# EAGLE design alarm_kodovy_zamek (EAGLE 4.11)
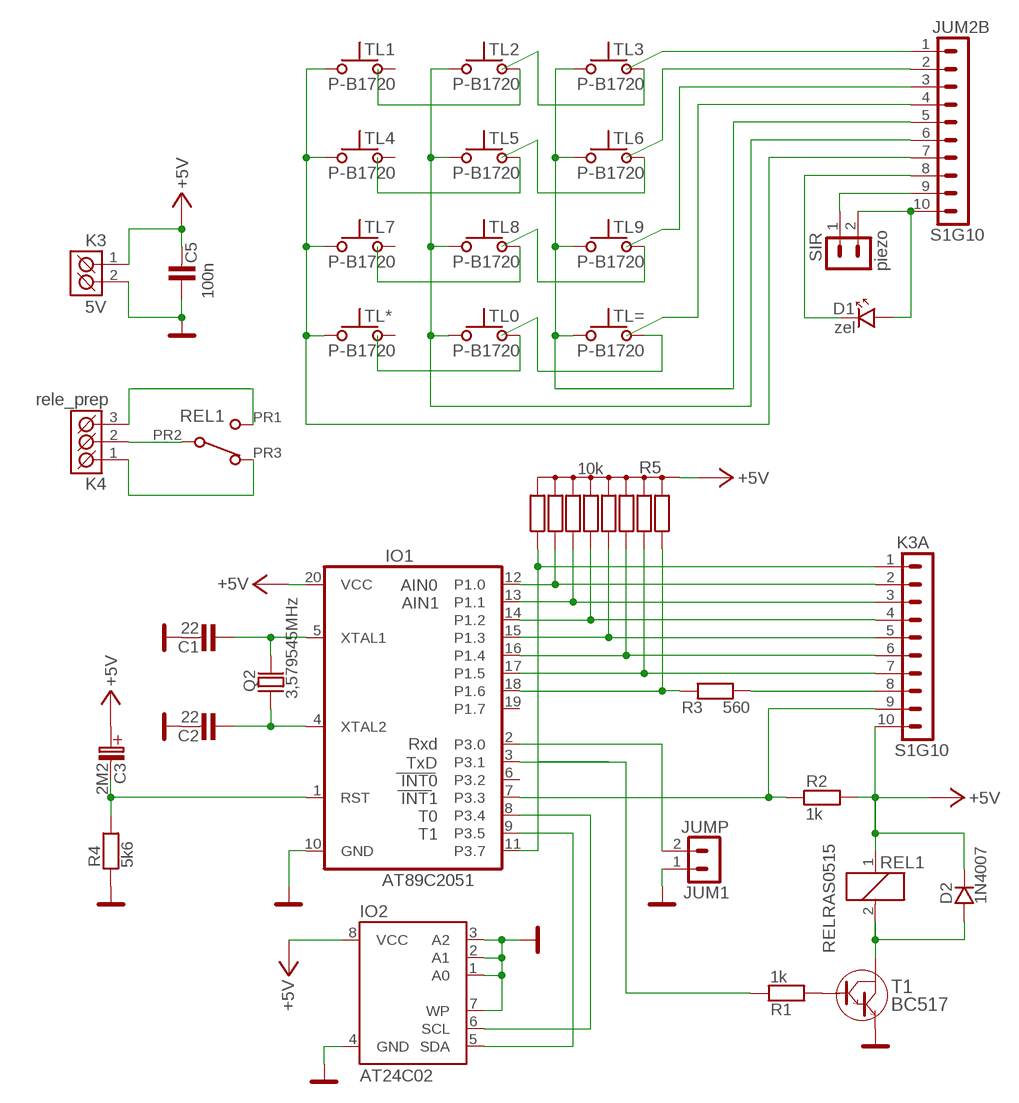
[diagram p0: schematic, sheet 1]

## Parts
C1  22  C-KERAMIK_5  [C-5]
C2  22  C-KERAMIK_5  [C-5]
C3  2M2  C-ELEKTROLYT_2  [C-EL_2]
C5  100n  C-KERAMIK_SMD_1206  [1206]
D1  zel  LED_3  [LED_3]
D2  1N4007  1N4007_SMD_SM-1  [SM-1]
IO1  AT89C2051  [DIL20]
IO2  AT24C02  AT24CP  [DIL08]
JUM1  JUMP  S1G2_JUMP  [S1G2_JUM]
JUM2B  S1G10  S1G10_JUMP  [S1G10_JU]
K3  5V  ARK500/2  [ARK500/2]
K3A  S1G10  S1G10_JUMP  [S1G10_JU]
K4  rele_prep  ARK500/3  [ARK500/3]
Q2  3,579545MHz  Q_HC-49U  [HC-49U]
R1  1k  R_SMD_1206  [1206]
R2  1k  R_SMD_1206  [1206]
R3  560  R_SMD_1206  [1206]
R4  5k6  R_7,5  [R-7,5]
R5  10k  RR_8X_A  [RR_8X_A]
REL1  RELRAS0515  RELRAS15  [RELE_RAS]
SIR  piezo  S1G2_JUMP  [S1G2_JUM]
T1  BC517  [TO-92]
TL0  P-B1720  [P-B1720]
TL1  P-B1720  [P-B1720]
TL2  P-B1720  [P-B1720]
TL3  P-B1720  [P-B1720]
TL4  P-B1720  [P-B1720]
TL5  P-B1720  [P-B1720]
TL6  P-B1720  [P-B1720]
TL7  P-B1720  [P-B1720]
TL8  P-B1720  [P-B1720]
TL9  P-B1720  [P-B1720]
TL*  P-B1720  [P-B1720]
TL=  P-B1720  [P-B1720]

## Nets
+5V: C3.C+(C_EL+) C5.2 D2.K IO1.20(VCC) IO2.8(VCC) K3.1(K1) K3A.10 R2.2 R5.1(R) REL1.1(RE:C1)
GND: C1.2 C2.2 C5.1 IO1.10(GND) IO2.1(A0) IO2.2(A1) IO2.3(A2) IO2.4(GND) IO2.7(WP) JUM1.1 K3.2(K2) R4.1 T1.3(E)
K3B: D1.A JUM2B.10 SIR.2
N$1: IO1.11(P3.7) K3A.1 R5.9(R8)
N$2: IO1.18(P1.6) R3.1 R5.2(R1)
N$3: C1.1 IO1.5(XTAL1) Q2.2
N$4: C2.1 IO1.4(XTAL2) Q2.1
N$5: IO1.12(P1.0) K3A.2 R5.8(R7)
N$6: IO1.13(P1.1) K3A.3 R5.7(R6)
N$7: IO1.14(P1.2) K3A.4 R5.6(R5)
N$8: IO1.15(P1.3) K3A.5 R5.5(R4)
N$9: IO1.16(P1.4) K3A.6 R5.4(R3)
N$10: IO1.17(P1.5) K3A.7 R5.3(R2)
N$11: C3.C-(C_EL-) IO1.1(RST) R4.2
N$12: K4.3(K3) REL1.PR1
N$13: K4.1(K1) REL1.PR3
N$14: K3A.8 R3.2
N$15: IO1.8(P3.4) IO2.6(SCL)
N$16: IO1.9(P3.5) IO2.5(SDA)
N$17: R1.2 T1.2(B)
N$18: IO1.7(P3.3) K3A.9 R2.1
N$19: IO1.2(P3.0) JUM1.2
N$20: IO1.3(P3.1) R1.1
N$21: D2.A REL1.2(RE:C2) T1.1(C)
N$22: JUM2B.9 SIR.1
N$23: D1.K JUM2B.8
N$24: K4.2(K2) REL1.PR2
N$26: TL2.4 TL3.2
N$27: JUM2B.1 TL3.4
N$28: TL1.4 TL2.2
N$29: TL5.4 TL6.2
N$30: TL4.4 TL5.2
N$31: JUM2B.2 TL6.4
N$32: JUM2B.7 TL1.1 TL4.1 TL7.1 TL*.1
N$33: JUM2B.3 TL9.4
N$34: JUM2B.4 TL=.4
N$35: JUM2B.5 TL3.1 TL6.1 TL9.1 TL=.1
N$36: JUM2B.6 TL0.1 TL2.1 TL5.1 TL8.1
N$37: TL0.4 TL=.2
N$38: TL7.4 TL8.2
N$39: TL8.4 TL9.2
N$40: TL0.2 TL*.4
Unconnected: IO1.6(P3.2) IO1.19(P1.7) TL0.3 TL1.2 TL1.3 TL2.3 TL3.3 TL4.2 TL4.3 TL5.3 TL6.3 TL7.2 TL7.3 TL8.3 TL9.3 TL*.2 TL*.3 TL=.3

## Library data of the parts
C1 C2 C5 = #PaJa_13:C-KERAMIK: Kondenzator - keramicky
C3 = #PaJa_13:C-ELEKTROLYT: Kondenzator - elektrolyticky
D1 = #PaJa_13:LED: LED - jednobarevna
D2 = #PaJa_13:1N4007: Usmernovaci dioda - 1A, 1000V
IO1 = #PaJa_13:AT89C2051: &micro;-kontroler ATMEL - 2kB
IO2 = atmel:AT24C*: 2-wire serial EEPROM
JUM1 SIR = #PaJa_13:S1G2_JUMP: Radove konektory - koliky - 2x
JUM2B K3A = #PaJa_13:S1G10_JUMP: Radove konektory - koliky - 10x
K3 = #PaJa_15:ARK500/2: Svorkovnice - roztec 5mm - dvojita
K4 = #PaJa_15:ARK500/3: Svorkovnice - roztec 5mm - trojita
Q2 = #PaJa_13:Q_HC-49U: Krystal - 1MHz - 48MHz
R1-R4 = #PaJa_13:R: Rezistor
R5 = #PaJa_13:RR_8X_A: Odporova sit - 8x - spol. vyvod
REL1 = #PaJa_13:RELRAS??15: RELE - 1x prepinaci, 5V, 12V, 24V max. spinany proud = 15A
T1 = #PaJa_13:BC517
TL0 TL1-TL9 TL* TL= = #PaJa_13:P-B1720: &micro;-tlacitko

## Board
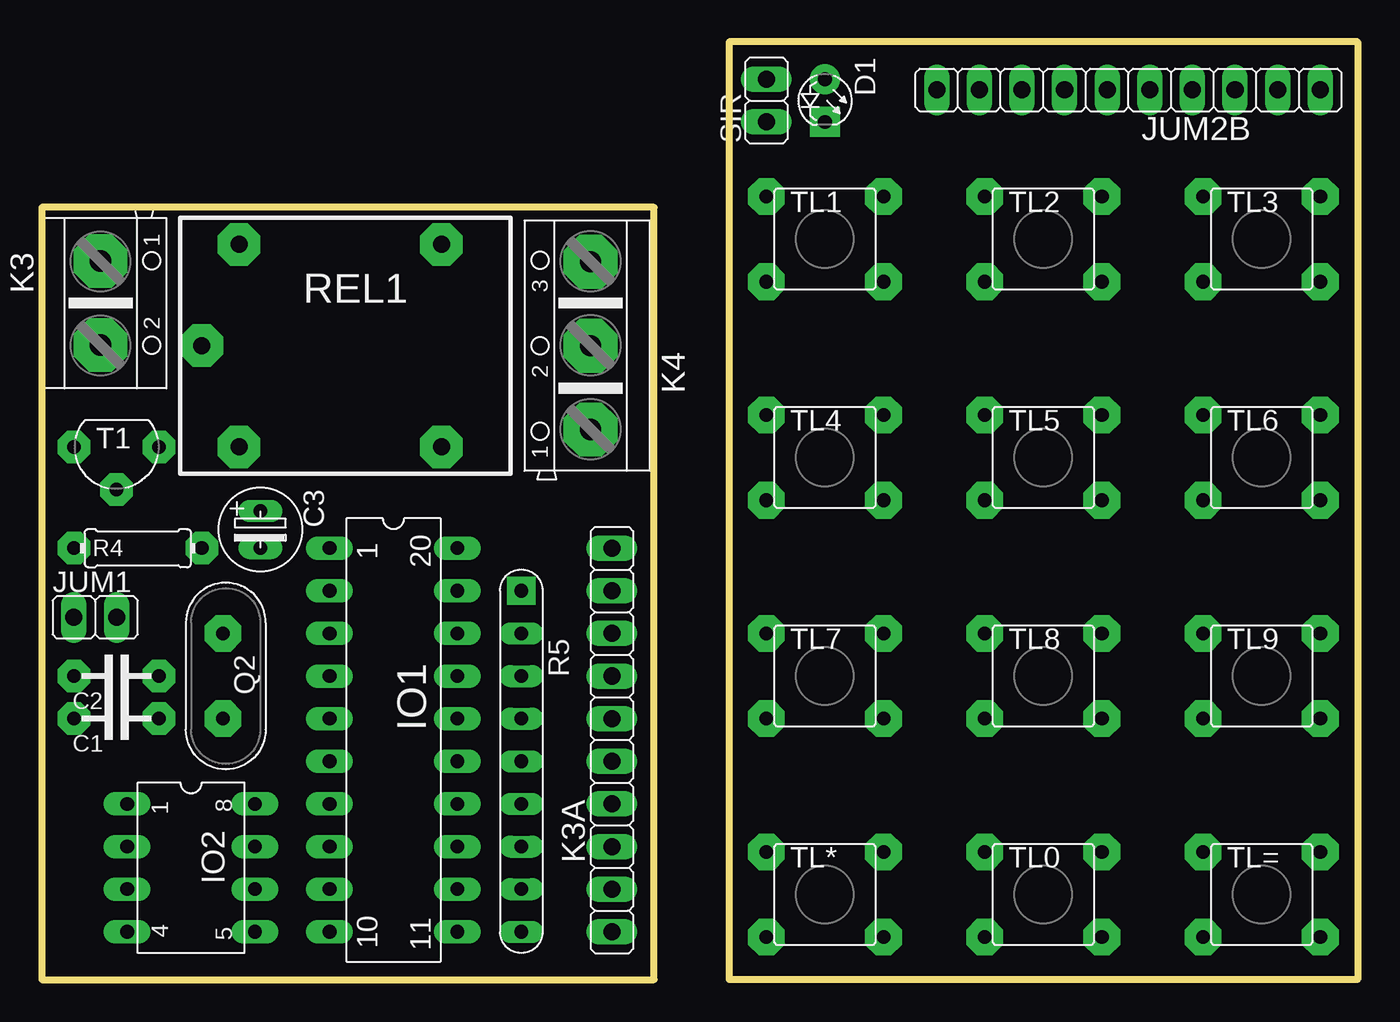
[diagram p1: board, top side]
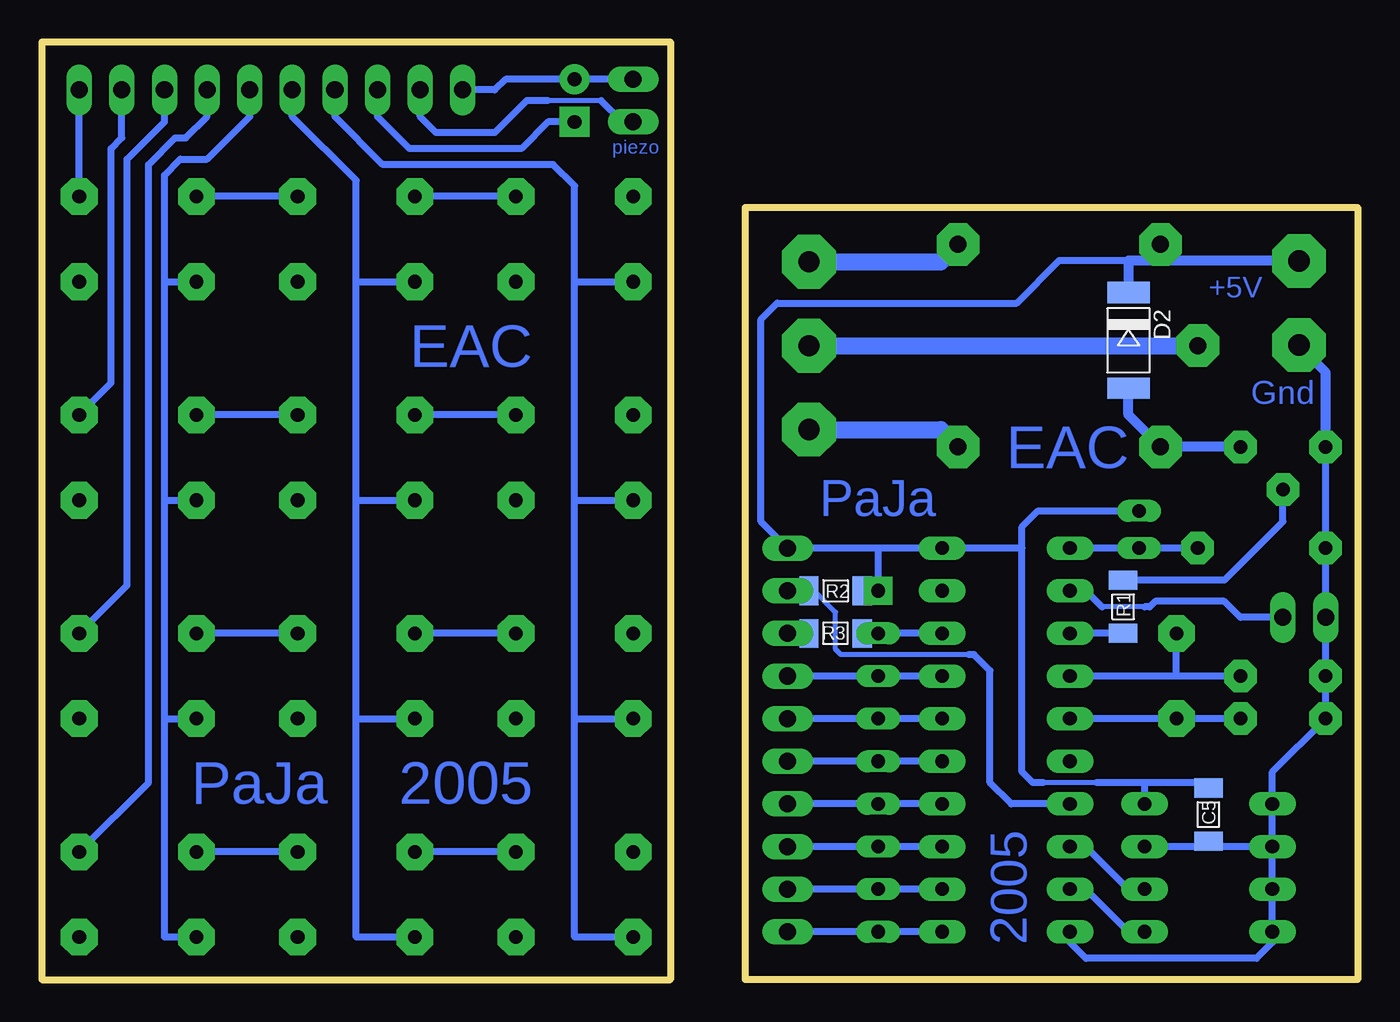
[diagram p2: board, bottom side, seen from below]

Size 78.42 x 55.88 mm. Coordinates in mm from the lower left corner, seen from the top.
Outline: 0,0 36.5,0 36.5,46.03 0,46.03 0,0
Outline: 78.42,55.88 40.96,55.88 40.96,0 78.42,0 78.42,55.88
Copper layers (1*16): Top 0.035mm / dielectric 1.5mm / Bottom 0.035mm
Design rules "default": minimum track width 10mil, minimum drill 24mil, track to track 8mil, track to pad 8mil, pad to pad 8mil, via to via 8mil, smd to smd 8mil, copper to edge 40mil, drill to drill 8mil, minimum pad ring 10mil, minimum via ring 8mil, stop-mask expansion 4mil, vias tented up to drill 0mil, thermal gap 10mil

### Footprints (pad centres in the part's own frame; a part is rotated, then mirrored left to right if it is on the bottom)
C-5 = drill 0.813 pad 1.93 octagon: 1 -2.54,0; 2 2.54,0
C-EL_2 = drill 0.813 pad 1.27 long: C+ 0,0; C- 2.223,0
1206 = smd 1.143 x 1.702: 1 -1.587,0; 2 1.587,0
LED_3 = drill 0.813 pad 1.778 round: A -1.27,0 | drill 0.813 pad 1.778 square: K 1.27,0
SM-1 = smd 1.27 x 2.54: A 2.54,0; K -3.175,0
DIL20 = drill 0.813 pad 1.4 long: 1 -11.43,-3.81; 2 -8.89,-3.81; 3 -6.35,-3.81; 4 -3.81,-3.81; 5 -1.27,-3.81; 6 1.27,-3.81; 7 3.81,-3.81; 8 6.35,-3.81; 9 8.89,-3.81; 10 11.43,-3.81; 11 11.43,3.81; 12 8.89,3.81; 13 6.35,3.81; 14 3.81,3.81; 15 1.27,3.81; 16 -1.27,3.81; 17 -3.81,3.81; 18 -6.35,3.81; 19 -8.89,3.81; 20 -11.43,3.81
DIL8 = drill 0.813 pad 1.4 long: 1 -3.81,-3.81; 2 -1.27,-3.81; 3 1.27,-3.81; 4 3.81,-3.81; 5 3.81,3.81; 6 1.27,3.81; 7 -1.27,3.81; 8 -3.81,3.81
S1G2_JUM = drill 1.016 pad 1.27 long: 1 -1.27,0; 2 1.27,0
S1G10_JU = drill 1.016 pad 1.27 long: 1 -11.43,0; 2 -8.89,0; 3 -6.35,0; 4 -3.81,0; 5 -1.27,0; 6 1.27,0; 7 3.81,0; 8 6.35,0; 9 8.89,0; 10 11.43,0
ARK500/2 = drill 1.27 pad 3.2 octagon: 1 -2.5,0; 2 2.5,0
ARK500/3 = drill 1.27 pad 3.2 octagon: 1 -5,0; 2 0,0; 3 5,0
HC-49U = drill 0.813 pad 2.184 octagon: 1 -2.54,0; 2 2.54,0
R-7,5 = drill 0.813 pad 1.93 octagon: 1 -3.81,0; 2 3.81,0
RR_8X_A = drill 0.813 pad 1.676 square: 1 -10.16,0 | drill 0.813 pad 1.27 long: 2 -7.62,0; 3 -5.08,0; 4 -2.54,0; 5 0,0; 6 2.54,0; 7 5.08,0; 8 7.62,0; 9 10.16,0
RELE_RAS = drill 1.016 pad 2.54 octagon: 1 0,12.065; 2 0,0; PR1 12.065,12.065; PR2 -2.223,6.032; PR3 12.065,0
TO-92 = drill 0.813 pad 1.93 octagon: 1 0,2.54; 2 2.54,0; 3 0,-2.54
P-B1720 = drill 0.813 pad 2.184 octagon: 1 -3.493,-2.54; 2 -3.493,2.54; 3 3.493,-2.54; 4 3.493,2.54

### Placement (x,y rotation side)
C1  4.45,15.56 180 top
C2  4.45,18.1 180 top
C3  13.02,27.94 270 top
C5  8.89,9.84 90 bottom
D1  46.67,52.39 270 top
D2  13.65,37.78 270 bottom
IO1  20.95,14.29 270 top
IO2  AT24C02  [DIL8]  8.89,6.67 270 top
JUM1  3.17,21.59 0 top
JUM2B  64.77,53.02 180 top
K3  3.49,40.32 270 top
K3A  33.97,14.29 90 top
K4  32.7,37.78 90 top
Q2  10.79,18.1 270 top
R1  13.97,22.23 90 bottom
R2  31.11,23.18 0 bottom
R3  31.11,20.64 180 bottom
R4  5.71,25.72 0 top
R5  28.57,13.02 270 top
REL1  11.75,31.75 0 top
SIR  43.18,52.39 90 top
T1  4.45,31.75 270 top
TL0  59.69,5.08 0 top
TL1  46.67,44.13 0 top
TL2  59.69,44.13 0 top
TL3  72.71,44.13 0 top
TL4  46.67,31.11 0 top
TL5  59.69,31.11 0 top
TL6  72.71,31.11 0 top
TL7  46.67,18.1 0 top
TL8  59.69,18.1 0 top
TL9  72.71,18.1 0 top
TL*  46.67,5.08 0 top
TL=  72.71,5.08 0 top

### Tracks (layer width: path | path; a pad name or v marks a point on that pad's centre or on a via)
+5V
  Bottom 0.305: 15.56,11.75 18.73,11.75
  Bottom 0.406: 20,25.72 IO1.20 28.57,25.72 | C3.C+ 19.05,27.94 20,26.99 20,25.72 | 13.65,42.86 17.78,42.86 20.32,40.32 34.61,40.32 35.56,39.37 35.56,27.3 K3A.10 28.57,25.72 | 28.57,25.72 R5.1 R2.2 | 20,25.72 20,12.38 19.37,11.75 18.73,11.75 | 12.7,11.75 15.56,11.75 | 12.7,11.75 IO2.8 | C5.2 8.89,11.75 12.7,11.75
  Bottom 0.61: 11.75,42.86 REL1.1 | 11.75,42.86 13.65,42.86 D2.K | K3.1 3.49,42.86 11.75,42.86
GND
  Bottom 0.406: IO2.2 IO2.3 IO2.4 5.08,2.22 6.03,1.27 16.19,1.27 17.14,2.22 IO1.10 | IO2.2 IO2.1 5.08,12.38 C1.2 C2.2 JUM1.1 R4.1 T1.3 | IO2.2 8.89,7.94 | 8.89,7.94 IO2.7 | 8.89,7.94 C5.1
  Bottom 0.61: T1.3 1.91,36.2 3.49,37.78 K3.2
K3B
  Bottom 0.406: SIR.2 D1.A 50.8,53.66 51.44,53.02 JUM2B.10
N$1
  Bottom 0.406: IO1.11 R5.9 K3A.1
N$2
  Bottom 0.406: R3.1 R5.2 IO1.18
N$3
  Bottom 0.406: C1.1 Q2.2 IO1.5
N$4
  Bottom 0.406: C2.1 10.79,18.1 | 10.79,18.1 IO1.4 | 10.79,18.1 Q2.1
N$5
  Bottom 0.406: IO1.12 R5.8 K3A.2
N$6
  Bottom 0.406: IO1.13 R5.7 K3A.3
N$7
  Bottom 0.406: IO1.14 R5.6 K3A.4
N$8
  Bottom 0.406: IO1.15 R5.5 K3A.5
N$9
  Bottom 0.406: IO1.16 R5.4 K3A.6
N$10
  Bottom 0.406: IO1.17 R5.3 K3A.7
N$11
  Bottom 0.406: R4.2 C3.C- IO1.1
N$12
  Bottom 1.016: K4.3 24.84,42.78 REL1.PR1
N$13
  Bottom 1.016: K4.1 24.84,32.78 REL1.PR3
N$14
  Bottom 0.406: R3.2 K3A.8
N$15
  Bottom 0.406: IO1.8 16.19,7.94 13.65,5.4 IO2.6
N$16
  Bottom 0.406: IO1.9 16.19,5.4 13.65,2.86 IO2.5
N$17
  Bottom 0.406: R1.2 7.94,23.81 4.45,27.3 T1.2
N$18
  Bottom 0.305: R2.1 32.38,23.18 31.11,21.91 31.11,19.68 30.8,19.37 23.18,19.37
  Bottom 0.406: R2.1 K3A.9 | IO1.7 20.64,10.48 21.91,11.75 21.91,18.41 22.86,19.37 23.18,19.37
N$19
  Bottom 0.305: 12.7,22.23 15.24,22.23
  Bottom 0.406: IO1.2 16.19,23.18 15.24,22.23 | JUM1.2 6.99,21.59 7.94,22.54 12.06,22.54 12.38,22.23 12.7,22.23
N$20
  Bottom 0.406: R1.1 IO1.3
N$21
  Bottom 0.61: D2.A 13.65,33.66 REL1.2 T1.1
N$22
  Bottom 0.305: 45.09,52.39 48.26,52.39
  Bottom 0.406: JUM2B.9 55.88,51.44 54.93,50.48 51.44,50.48 49.53,52.39 48.26,52.39 | 45.09,52.39 43.81,51.12 SIR.1
N$23
  Bottom 0.406: JUM2B.8 58.42,51.44 56.52,49.53 49.85,49.53 48.26,51.12 D1.K
N$24
  Bottom 1.016: K4.2 REL1.PR2
N$26
  Bottom 0.406: TL2.4 TL3.2
N$27
  Bottom 0.406: TL3.4 JUM2B.1
N$28
  Bottom 0.406: TL1.4 TL2.2
N$29
  Bottom 0.406: TL5.4 TL6.2
N$30
  Bottom 0.406: TL4.4 TL5.2
N$31
  Bottom 0.406: TL6.4 74.3,35.56 74.3,49.53 73.66,50.16 JUM2B.2
N$32
  Bottom 0.406: 46.67,41.59 TL1.1 | 46.67,15.56 46.67,2.54 TL*.1 | 46.67,15.56 46.67,28.57 | 46.67,28.57 46.67,41.59 | 46.67,28.57 TL4.1 | 46.67,15.56 TL7.1 | 46.67,41.59 46.67,47.31 47.94,48.58 58.1,48.58 60.96,51.44 JUM2B.7
N$33
  Bottom 0.406: TL9.4 73.34,23.5 73.34,48.9 71.12,51.12 JUM2B.3
N$34
  Bottom 0.406: TL=.4 72.07,11.75 72.07,48.58 70.48,50.16 69.85,50.16 68.58,51.44 JUM2B.4
N$35
  Bottom 0.406: TL=.1 71.12,2.54 71.12,15.56 | 71.12,15.56 71.12,28.57 | 71.12,28.57 71.12,41.59 | 71.12,41.59 TL3.1 | 71.12,15.56 TL9.1 | 71.12,28.57 TL6.1 | JUM2B.5 66.04,51.44 68.58,48.9 70.17,48.9 71.12,47.94 71.12,41.59
N$36
  Bottom 0.406: TL0.1 59.69,2.54 59.69,15.56 | 59.69,15.56 59.69,28.57 | 59.69,28.57 59.69,41.59 | 59.69,41.59 TL2.1 | 59.69,28.57 TL5.1 | 59.69,15.56 TL8.1 | JUM2B.6 63.5,51.44 59.69,47.62 59.69,41.59
N$37
  Bottom 0.406: TL0.4 TL=.2
N$38
  Bottom 0.406: TL7.4 TL8.2
N$39
  Bottom 0.406: TL8.4 TL9.2
N$40
  Bottom 0.406: TL*.4 TL0.2

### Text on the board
Bottom: piezo | +5V | EAC | Gnd | EAC | PaJa | 2005 | PaJa | 2005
